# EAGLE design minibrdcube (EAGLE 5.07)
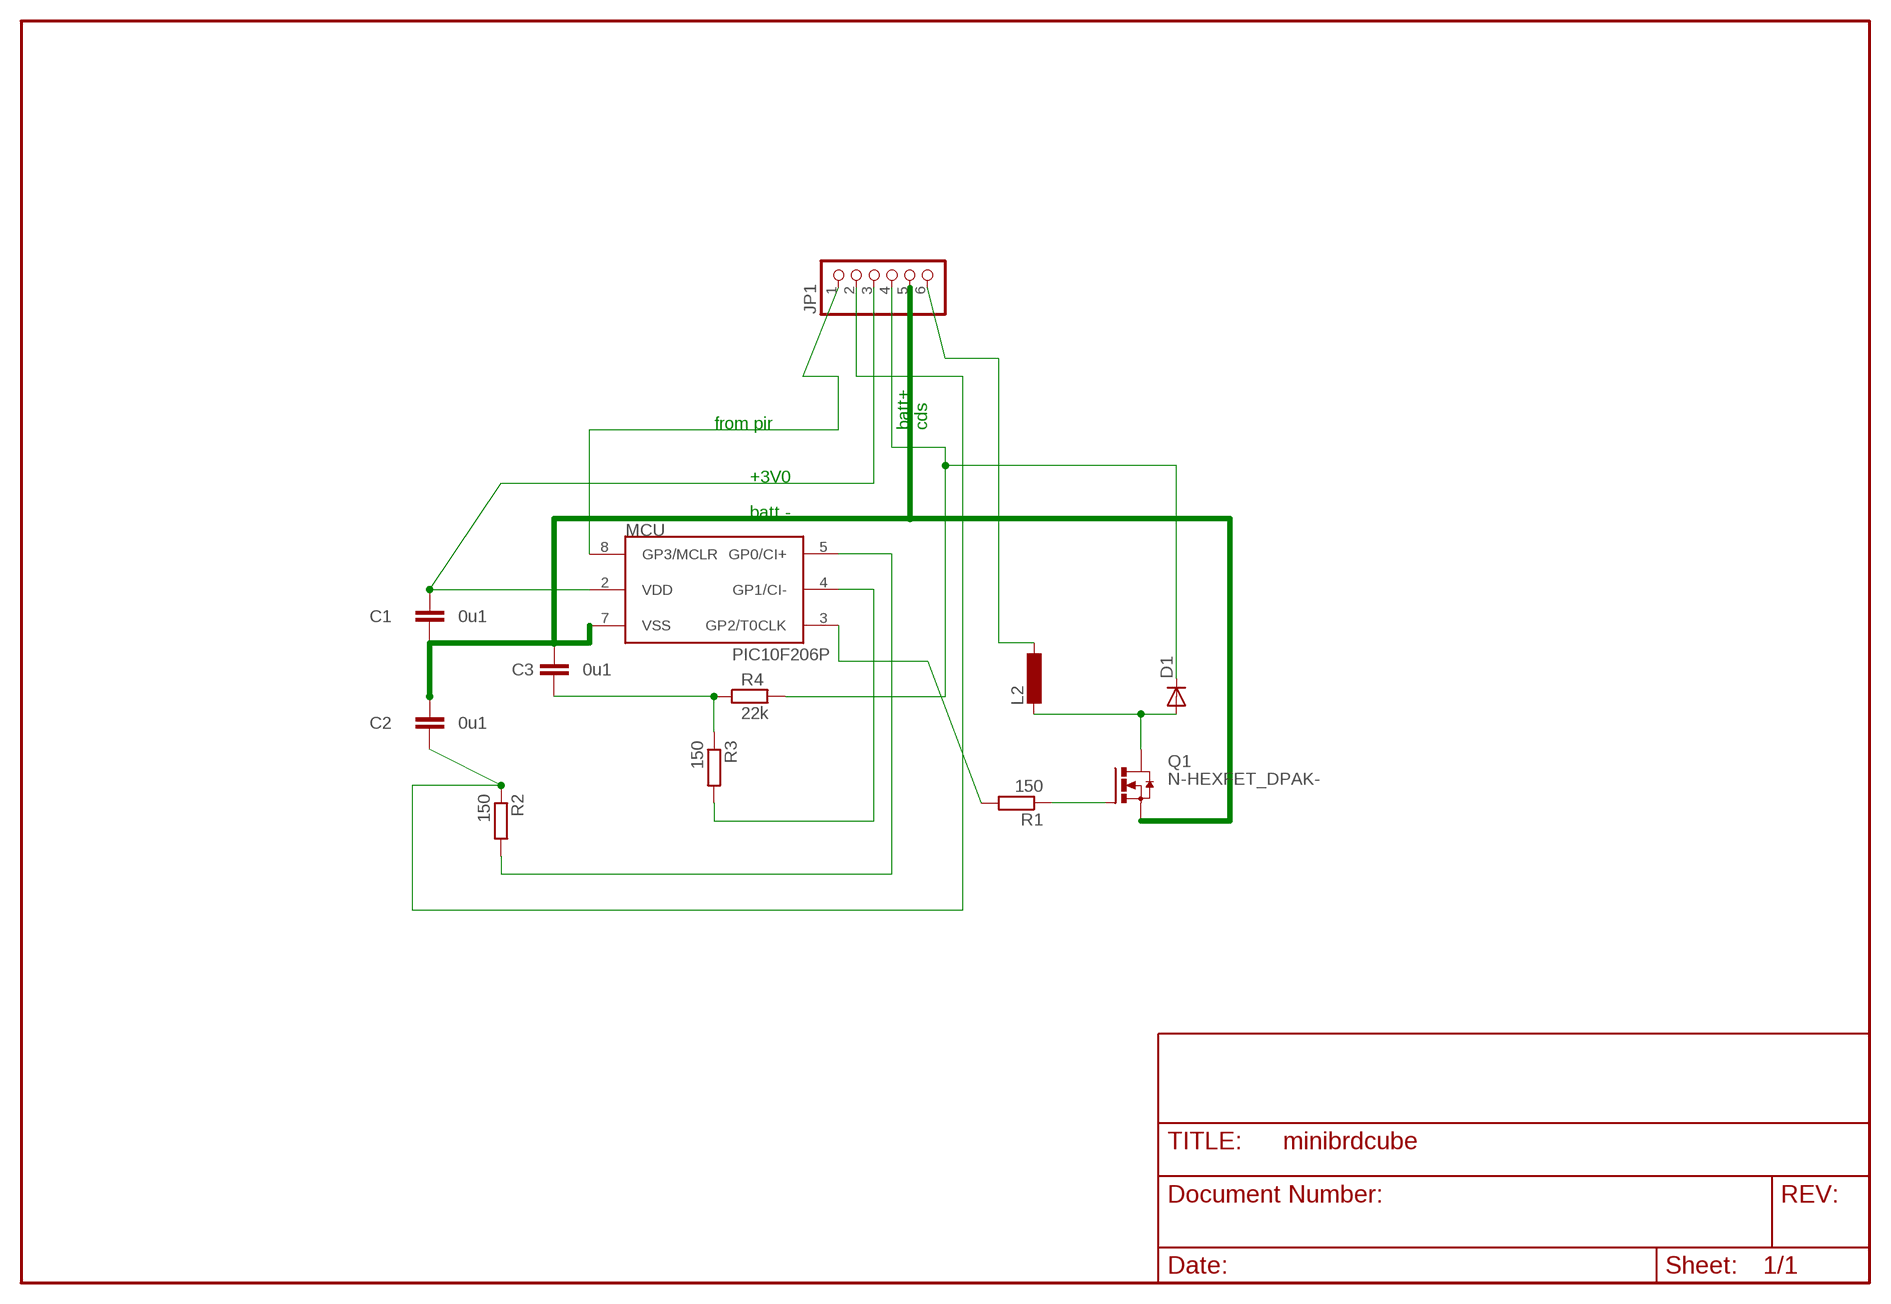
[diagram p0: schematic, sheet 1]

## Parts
C1  0u1  C-EUC1206  [C1206]
C2  0u1  C-EUC1206  [C1206]
C3  0u1  C-EUC1206  [C1206]
D1  DIODE-SMC  [SMC]
JP1  PINHD-1X6  [1X06BOX]
L2  L-EUPIS2816  [PIS2816]
MCU  PIC10F206P  [DIL8]
Q1  N-HEXFET_DPAK-  [TO252]
R1  150  R-EU_R1206  [R1206]
R2  150  R-EU_R1206  [R1206]
R3  150  R-EU_R1206  [R1206]
R4  22k  R-EU_R1206  [R1206]

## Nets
N$2: MCU.5(GP0/CI+) R2.2
N$3: D1.C JP1.4 R4.2
N$4: MCU.4(GP1/CI-) R3.2
N$5: D1.A L2.2 Q1.3(D)
N$6: C1.2 JP1.3 MCU.2(VDD)
N$7: Q1.1(G) R1.1
N$8: JP1.6 L2.1
N$10: C3.1 R3.1 R4.1
N$11: C2.1 JP1.2 R2.1
N$13: JP1.1 MCU.8(GP3/MCLR)
N$14: MCU.3(GP2/T0CLK) R1.2
VSS: C1.1 C2.2 C3.2 JP1.5 MCU.7(VSS) Q1.2(S)

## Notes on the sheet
- from pir | batt+ | cds
- +3V0
- batt -

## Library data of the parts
C1-C3 = rcl:C-EU: CAPACITOR, European symbol
D1 = diode-1:DIODE-: DIODE
JP1 = pinhead:PINHD-1X6: PIN HEADER
L2 = rcl:L-EU: INDUCTOR, European symbol
MCU = microchip-3:PIC10F2*: uPC nW 0,25/0,5k Program Flash memory Comparator
Q1 = transistor-power:N-HEXFET_?-*: HEXFET® Power MOSFET
R1-R4 = rcl:R-EU_: RESISTOR, European symbol

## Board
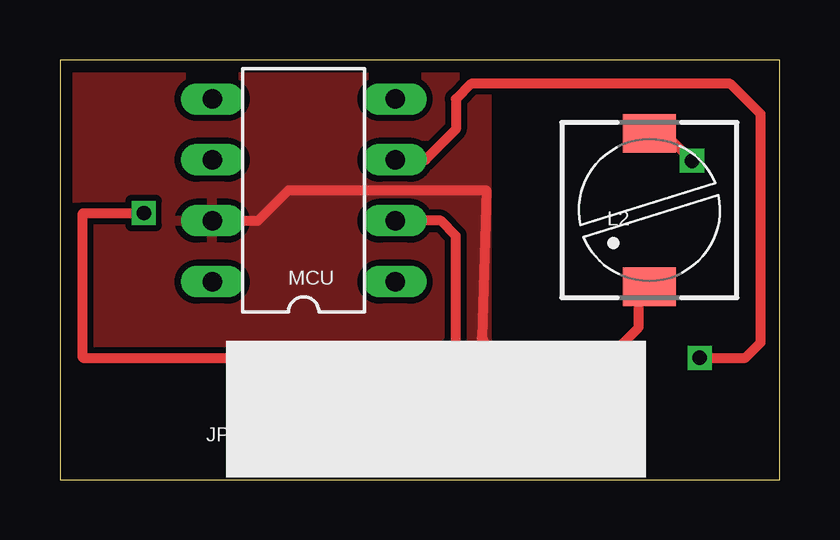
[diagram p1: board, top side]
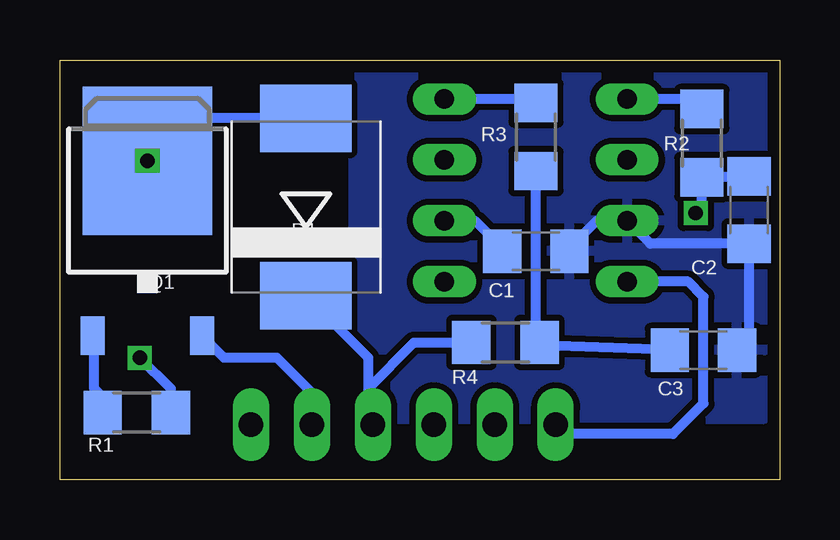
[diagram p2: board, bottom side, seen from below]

Size 30 x 17.5 mm. Coordinates in mm from the lower left corner, seen from the top.
Outline: 0,0 30,0 30,17.5 0,17.5 0,0
Copper layers (1*16): Top 0.035mm / dielectric 1.5mm / Bottom 0.035mm
Design rules "default *": minimum track width 10mil, minimum drill 24mil, track to track 8mil, track to pad 8mil, pad to pad 8mil, via to via 8mil, smd to smd 8mil, copper to edge 20mil, drill to drill 8mil, minimum pad ring 10mil, minimum via ring 8mil, stop-mask expansion 4mil, vias tented up to drill 0mil, thermal gap 10mil

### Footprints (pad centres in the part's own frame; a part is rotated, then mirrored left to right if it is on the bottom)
C1206 = smd 1.6 x 1.8: 1 -1.4,0; 2 1.4,0
SMC = smd 2.8 x 3.8: A 3.7,0; C -3.7,0
1X06BOX = drill 1.016 long: 1 -6.35,0; 2 -3.81,0; 3 -1.27,0; 4 1.27,0; 5 3.81,0; 6 6.35,0
PIS2816 = smd 2.2 x 1.6: 1 0,3.2; 2 0,-3.2
DIL8 = drill 0.813 long: 1 -3.81,-3.81; 2 -1.27,-3.81; 3 1.27,-3.81; 4 3.81,-3.81; 5 3.81,3.81; 6 1.27,3.81; 7 -1.27,3.81; 8 -3.81,3.81
TO252 = smd 1 x 1.6: 1 -2.28,-3.53; 2 2.28,-3.53 | smd 5.4 x 6.2: 3 0,3.77
R1206 = smd 1.6 x 1.803: 1 -1.422,0; 2 1.422,0

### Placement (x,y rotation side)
C1  10.16,9.53 180 bottom
C2  1.27,11.24 270 bottom
C3  3.17,5.4 0 bottom
D1  19.75,11.37 90 bottom
JP1  15.68,2.29 0 top
L2  24.57,11.24 180 top
MCU  10.16,12.06 90 top
Q1  26.35,9.53 0 bottom
R1  26.8,2.79 0 bottom
R2  3.24,14.03 90 bottom
R3  10.16,14.29 90 bottom
R4  11.43,5.71 180 bottom

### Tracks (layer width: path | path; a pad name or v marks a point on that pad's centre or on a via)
N$2
  Bottom 0.406: MCU.5 3.66,15.88 R2.2
N$3
  Bottom 0.406: D1.C 19.73,7.67 17.14,5.08 17.14,3.81 | 17.14,3.81 17.14,2.48 JP1.4 | R4.2 15.24,5.71 17.14,3.81
N$4
  Bottom 0.406: MCU.4 10.32,15.88 R3.2
N$5  (via drill 0.6)
  Top 0.406: L2.2 25.21,14.44 Q1.3
  Bottom 0.406: D1.A 24.58,15.07 Q1.3 26.35,13.65 27.3,14.61 27.3,13.34
  other vias: 26.35,13.29
N$6
  Top 0.406: JP1.3 14.41,3.62 16.51,5.71 16.51,10.16 15.88,10.79 MCU.2
  Bottom 0.406: C1.2 11.56,9.65 12.7,10.79 MCU.2
N$7
  Bottom 0.406: R1.1 28.22,3.45 28.57,3.81 28.57,5.94 Q1.1
N$8
  Top 0.406: JP1.6 22.04,4.25 24.13,6.35 24.13,7.59 L2.1
N$10
  Bottom 0.406: C3.1 9.88,5.58 R4.1 10.16,5.87 R3.1
N$11  (via drill 0.6)
  Top 0.406: v3.49,11.11 0.95,11.11 0.95,5.08 10.79,5.08 12.06,3.81 12.06,2.48 JP1.2
  Bottom 0.406: C2.1 3.21,12.64 R2.1 3.24,11.37 v3.49,11.11
N$13
  Bottom 0.406: MCU.8 3.81,8.26 3.17,7.62 3.17,3.17 4.45,1.91 8.95,1.91 JP1.1
N$14  (via drill 0.6)
  Top 0.406: v26.67,5.08 28.57,5.08 29.21,5.71 29.21,15.24 27.94,16.51 17.14,16.51 16.51,15.88 16.51,14.61 15.24,13.34 MCU.3
  Bottom 0.406: R1.2 25.38,3.79 v26.67,5.08
VSS
  Top 0.406: MCU.7 8.26,10.79 9.53,12.06 17.78,12.06 17.59,5.91 JP1.5
  Bottom 0.406: C3.2 1.27,5.9 C2.2 5.39,9.84 MCU.7 7.62,10.79 8.76,9.65 C1.1 | JP1.5 19.49,3.62 20.95,5.08 23.16,5.08 Q1.2
  pour Bottom (isolate 0.254): 0.64,17.14 17.78,17.14 17.78,2.54 0.64,2.54
  pour Top (isolate 0.254): 0.64,17.14 17.78,17.14 17.78,2.54 0.64,2.54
